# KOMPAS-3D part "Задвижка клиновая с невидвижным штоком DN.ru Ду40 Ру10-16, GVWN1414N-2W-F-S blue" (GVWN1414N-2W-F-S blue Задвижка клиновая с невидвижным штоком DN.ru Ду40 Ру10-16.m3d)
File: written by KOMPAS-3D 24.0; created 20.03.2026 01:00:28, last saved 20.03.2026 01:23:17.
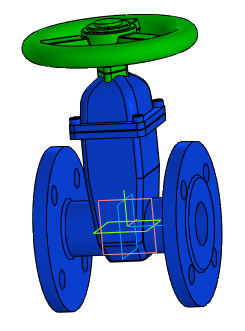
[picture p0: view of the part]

Document properties: Автор: R2D2; Полное имя файла: E:\Работа\Зайцев\GVWN1414N-2W-F-S blue Задвижка клиновая с невидвижным штоком DN.ru Ду40-300 Ру10-16\DN40\GVWN1414N-2W-F-S blue Задвижка клиновая с невидвижным штоком DN.ru Ду40 Ру10-16.m3d

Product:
- Part/product: Задвижка клиновая с невидвижным штоком DN.ru Ду40 Ру10-16  | designation GVWN1414N-2W-F-S blue
    Масса: 7
    Раздел спецификации: Прочие изделия
    Примечание: D040-10578

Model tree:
1. Операция без истории:2

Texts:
  GVWN1414N-2W-F-S blue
